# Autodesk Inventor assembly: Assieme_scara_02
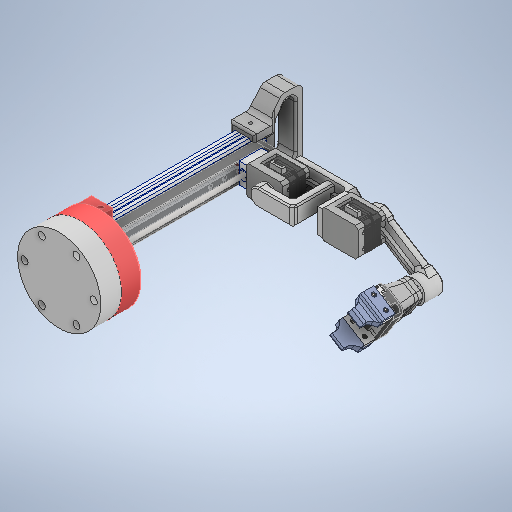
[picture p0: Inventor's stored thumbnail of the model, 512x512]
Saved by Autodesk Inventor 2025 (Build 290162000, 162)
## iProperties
Created: 2025-11
Part Number: Assieme_scara_02
Document SubType Name: Assembly
Designer: Ryzen5700u
Title: Assieme_scara_03.stp
Author: R5800u
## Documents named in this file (16)
- C:\Users\Ryzen5700u\Desktop\scara_06\Assieme_scara_05.iam
- C:\Users\Ryzen5700u\Desktop\scara_06\base1.ipt
- C:\Users\Ryzen5700u\Desktop\scara_06\blocco_motore1.ipt
- C:\Users\Ryzen5700u\Desktop\scara_06\AS 1420 - 1973 - M4 x 30.ipt
- C:\Users\Ryzen5700u\Desktop\scara_06\tslot 2040.ipt
- C:\Users\Ryzen5700u\Desktop\scara_06\Assieme_profilato.iam
- C:\Users\Ryzen5700u\Desktop\scara_06\maniglia.ipt
- C:\Users\Ryzen5700u\Desktop\scara_06\disco_120.ipt
- C:\Users\Ryzen5700u\Desktop\scara_06\gripper v3.iam
- C:\Users\Ryzen5700u\Desktop\scara_06\nema17_23mm.ipt
- C:\Users\Ryzen5700u\Desktop\scara_06\braccio_nema17.ipt
- C:\Users\Ryzen5700u\Desktop\scara_06\blocco_motore2.ipt
- C:\Users\Ryzen5700u\Desktop\scara_06\braccio_2_nema17.ipt
- C:\Users\Ryzen5700u\Desktop\scara_06\DUOPAN-DG.ipt
- C:\Users\Ryzen5700u\Documents\Inventor\Content Center Files\R2025\it-IT\BS 290 SKF(30)\BS 290 SKF - SKF 618_8.ipt
- C:\Users\Ryzen5700u\Desktop\scara_06\blocco_braccio_01.ipt
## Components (19 placed, 15 different names)
1. base1:1
2. blocco_motore1:1
3. AS 1420 - Metrico M4 x 30:1
4. AS 1420 - Metrico M4 x 30:2
5. AS 1420 - Metrico M4 x 30:3
6. AS 1420 - Metrico M4 x 30:4
7. tslot 2040:1 — Angolo:5
8. Assieme_profilato:1 [sub-assembly] — Coincidente:3, Angolo:1, Coincidente:4, Angolo:2
9. maniglia:1
10. disco_120:1
11. gripper v3:1 [sub-assembly] — Rotazionale:3, Angolo:3
12. nema17_23mm:1 — Coincidente:5, Allineato:1, Coincidente:6, Rotazionale:1
13. braccio_nema17:1 — Rotazionale:1, Coincidente:9, Allineato:3, Angolo:2, Angolo:5
14. blocco_motore2:1 — Coincidente:9, Allineato:3, Allineato:4
15. nema17_23mm:2 — Rotazionale:2
16. braccio_2_nema17:1 — Rotazionale:2, Rotazionale:3, Angolo:3
17. DUOPAN-DG:1 — Rotazionale:4
18. BS 290 SKF 618/8:1 — Rotazionale:5
19. blocco_braccio_01:1 — Rotazionale:5, Angolo:4
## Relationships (18: Mate 5, Angle 5, RevoluteJoint 5, Flush 3)
- Coincidente:3 [Mate]: Assieme_profilato:1
- Angolo:1 [Angle]: Assieme_profilato:1
- Coincidente:4 [Mate]: Assieme_profilato:1
- Coincidente:5 [Mate]: nema17_23mm:1
- Allineato:1 [Flush]: nema17_23mm:1
- Coincidente:6 [Mate]: nema17_23mm:1
- Rotazionale:1 [RevoluteJoint]: nema17_23mm:1 ↔ braccio_nema17:1
- Coincidente:9 [Mate]: braccio_nema17:1 ↔ blocco_motore2:1
- Allineato:3 [Flush]: braccio_nema17:1 ↔ blocco_motore2:1
- Rotazionale:2 [RevoluteJoint]: nema17_23mm:2 ↔ braccio_2_nema17:1
- Angolo:2 [Angle]: Assieme_profilato:1 ↔ braccio_nema17:1
- Allineato:4 [Flush]: blocco_motore2:1
- Rotazionale:3 [RevoluteJoint]: gripper v3:1 ↔ braccio_2_nema17:1
- Angolo:3 [Angle]: gripper v3:1 ↔ braccio_2_nema17:1
- Rotazionale:4 [RevoluteJoint]: DUOPAN-DG:1
- Rotazionale:5 [RevoluteJoint]: BS 290 SKF 618/8:1 ↔ blocco_braccio_01:1
- Angolo:4 [Angle]: blocco_braccio_01:1
- Angolo:5 [Angle]: tslot 2040:1 ↔ braccio_nema17:1
## Named parameters: d86_d83 = 0, d87_d81 = 0, d88_d79 = 21.15 mm
